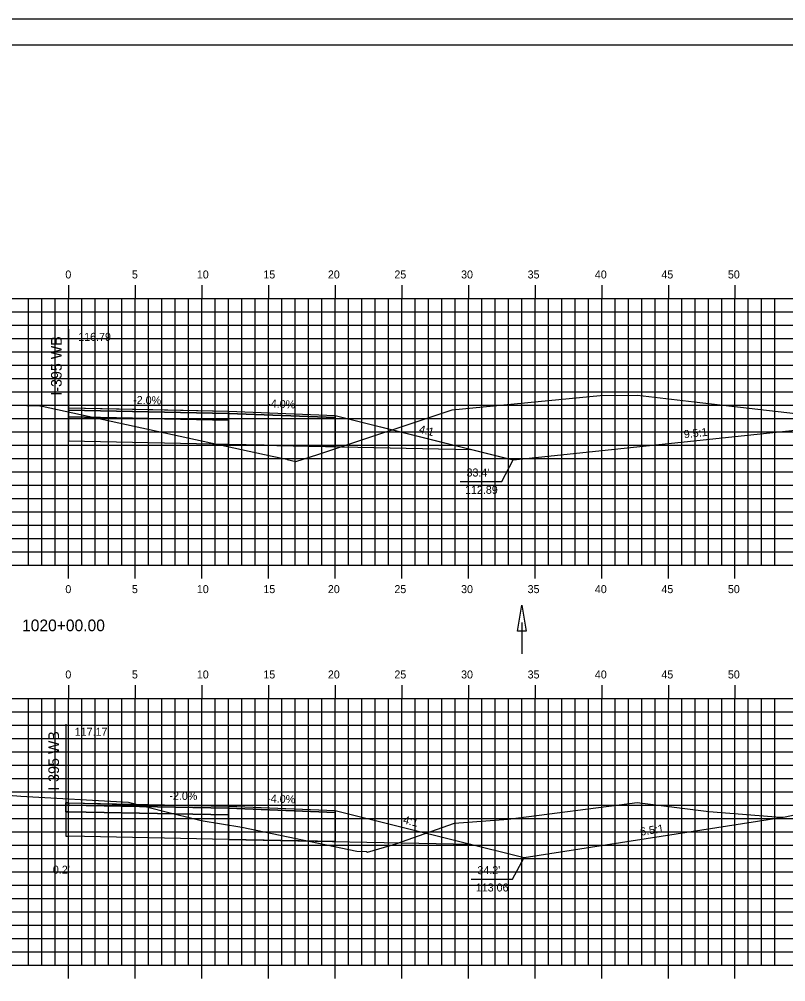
# Model space of a CAD drawing. Extents: x 853734 to 853906, y 365624 to 365734.
# Drawn here: x 853813.6 to 853871.1, y 365661.8 to 365734 of the extents above; entities that cross this region are included whole.
import ezdxf

# ---------------------------------------------------------------- set-up
doc = ezdxf.new("R2010")
doc.units = 0
for name, color, linetype in [('ANNOTATION', 7, 'Continuous'), ('BORDER', 7, 'Continuous'), ('D_Drainage_Ditch_Line', 7, 'Continuous'), ('D_Roadway_Centerline', 7, 'Continuous'), ('D_Roadway_Centerline_Text', 7, 'Continuous'), ('D_Roadway_Edge_Shoulder', 7, 'Continuous'), ('D_Roadway_Edge_TW', 7, 'Continuous'), ('D_Roadway_FinishedGrade', 7, 'Continuous'), ('D_Roadway_Pavement', 7, 'Continuous'), ('D_Roadway_SubGrade', 7, 'Continuous'), ('D_Text_Standard', 7, 'Continuous'), ('Default', 7, 'Continuous'), ('H_V ANNOTATION', 7, 'Continuous'), ('MAJOR', 7, 'Continuous'), ('MINOR', 7, 'Continuous'), ('PLOT BOUNDARY', 7, 'Continuous'), ('S_Roadway_Centerline', 7, 'Continuous')]:
    doc.layers.add(name, color=color, linetype=linetype)

msp = doc.modelspace()

# ---------------------------------------------------------------- linework, layer by layer
at = {"layer": 'ANNOTATION'}
for points in [[(853846.717, 365699.31), (853849.826, 365699.31), (853850.691, 365700.915)], [(853847.53, 365669.486), (853850.64, 365669.486), (853851.505, 365671.091)]]:
    msp.add_lwpolyline(points, dxfattribs=at)
at = {"layer": 'BORDER'}
msp.add_lwpolyline([(853742.331, 365627.027), (853902.331, 365627.027), (853902.331, 365732.027), (853742.331, 365732.027)], close=True, dxfattribs=at)
at = {"layer": 'D_Drainage_Ditch_Line'}
msp.add_line((853851.339, 365688.72), (853851.339, 365686.37), dxfattribs=at)
msp.add_lwpolyline([(853851.667, 365688.064), (853851.011, 365688.064), (853851.339, 365690.032)], close=True, dxfattribs=at)
at = {"layer": 'D_Roadway_Centerline'}
for p, q in [((853850.691, 365700.915), (853878.26, 365703.831)), ((853829.332, 365702.075), (853847.505, 365701.711)), ((853851.505, 365671.091), (853870.947, 365674.131)), ((853829.331, 365672.455), (853847.505, 365672.091))]:
    msp.add_line(p, q, dxfattribs=at)
for points in [[(853817.323, 365704.815), (853817.33, 365704.815), (853817.331, 365704.815), (853823.65, 365704.688), (853829.332, 365704.575), (853837.331, 365704.255)], [(853837.331, 365704.255), (853850.691, 365700.915)], [(853817.122, 365675.199), (853817.136, 365675.199), (853817.331, 365675.195), (853822.774, 365675.086), (853829.326, 365674.955), (853829.331, 365674.955), (853837.331, 365674.635)], [(853837.331, 365674.635), (853851.505, 365671.091)]]:
    msp.add_lwpolyline(points, dxfattribs=at)
at = {"layer": 'D_Roadway_Edge_Shoulder'}
for points in [[(853817.331, 365704.815), (853817.323, 365704.815), (853817.323, 365704.649), (853817.331, 365704.648)], [(853829.332, 365704.575), (853837.331, 365704.255), (853837.331, 365704.088), (853829.332, 365704.408)], [(853817.331, 365675.195), (853817.122, 365675.199), (853817.122, 365675.033), (853817.331, 365675.029)], [(853829.331, 365674.955), (853837.331, 365674.635), (853837.331, 365674.469), (853829.331, 365674.789)]]:
    msp.add_lwpolyline(points, close=True, dxfattribs=at)
at = {"layer": 'D_Roadway_Edge_TW'}
for points in [[(853817.331, 365704.815), (853829.332, 365704.575), (853829.332, 365704.408), (853817.331, 365704.648)], [(853817.331, 365675.195), (853829.331, 365674.955), (853829.331, 365674.789), (853817.331, 365675.029)]]:
    msp.add_lwpolyline(points, close=True, dxfattribs=at)
for points in [[(853829.332, 365704.575), (853829.332, 365704.408)], [(853829.331, 365674.955), (853829.331, 365674.789)]]:
    msp.add_lwpolyline(points, dxfattribs=at)
at = {"layer": 'D_Roadway_FinishedGrade'}
for p, q in [((853817.122, 365675.199), (853817.122, 365674.949)), ((853817.331, 365675.195), (853817.331, 365674.945)), ((853829.331, 365674.955), (853829.331, 365674.705)), ((853837.331, 365674.635), (853837.331, 365674.385))]:
    msp.add_line(p, q, dxfattribs=at)
at = {"layer": 'D_Roadway_Pavement'}
for points in [[(853817.331, 365704.648), (853817.323, 365704.649), (853817.323, 365704.149), (853817.331, 365704.148)], [(853817.331, 365704.648), (853829.332, 365704.408), (853829.332, 365703.908), (853817.331, 365704.148)], [(853817.331, 365675.029), (853817.122, 365675.033), (853817.122, 365674.533), (853817.331, 365674.529)], [(853817.331, 365675.029), (853829.331, 365674.789), (853829.331, 365674.289), (853817.331, 365674.529)]]:
    msp.add_lwpolyline(points, close=True, dxfattribs=at)
for points in [[(853829.332, 365704.408), (853829.332, 365703.908)], [(853829.332, 365704.408), (853829.332, 365703.908)], [(853829.331, 365674.789), (853829.331, 365674.289)], [(853829.331, 365674.789), (853829.331, 365674.289)]]:
    msp.add_lwpolyline(points, dxfattribs=at)
at = {"layer": 'D_Roadway_SubGrade'}
for p, q in [((853817.323, 365710.719), (853817.323, 365702.315)), ((853817.122, 365681.103), (853817.122, 365672.699))]:
    msp.add_line(p, q, dxfattribs=at)
for points in [[(853817.331, 365704.148), (853817.323, 365704.149), (853817.323, 365704.649), (853817.323, 365704.815), (853817.323, 365702.315), (853817.331, 365702.315)], [(853829.332, 365703.908), (853829.332, 365704.408), (853837.331, 365704.088), (853837.331, 365704.255), (853837.331, 365701.915), (853829.332, 365702.075)], [(853817.331, 365704.148), (853829.332, 365703.908), (853829.332, 365702.075), (853817.331, 365702.315)], [(853817.331, 365674.529), (853817.122, 365674.533), (853817.122, 365675.033), (853817.122, 365675.199), (853817.122, 365672.699), (853817.331, 365672.695)], [(853829.331, 365674.289), (853829.331, 365674.789), (853837.331, 365674.469), (853837.331, 365674.635), (853837.331, 365672.295), (853829.331, 365672.455)], [(853817.331, 365674.529), (853829.331, 365674.289), (853829.331, 365672.455), (853817.331, 365672.695)]]:
    msp.add_lwpolyline(points, close=True, dxfattribs=at)
for points in [[(853829.332, 365703.908), (853829.332, 365702.075)], [(853829.331, 365674.289), (853829.331, 365672.455)]]:
    msp.add_lwpolyline(points, dxfattribs=at)
at = {"layer": 'Default'}
msp.add_lwpolyline([(853837.331, 365704.255), (853841.331, 365703.255), (853850.154, 365701.049)], dxfattribs=at)
at = {"layer": 'MAJOR'}
for p, q in [((853817.331, 365714.029), (853817.331, 365713.027)), ((853822.331, 365714.029), (853822.331, 365713.027)), ((853827.331, 365714.029), (853827.331, 365713.027)), ((853832.331, 365714.029), (853832.331, 365713.027)), ((853837.331, 365714.029), (853837.331, 365713.027)), ((853842.331, 365714.029), (853842.331, 365713.027)), ((853847.331, 365714.029), (853847.331, 365713.027)), ((853852.331, 365714.029), (853852.331, 365713.027)), ((853857.331, 365714.029), (853857.331, 365713.027)), ((853862.331, 365714.029), (853862.331, 365713.027)), ((853867.331, 365714.029), (853867.331, 365713.027)), ((853747.331, 365713.027), (853887.331, 365713.027)), ((853747.331, 365713.027), (853887.331, 365713.027)), ((853817.331, 365693.027), (853817.331, 365713.027)), ((853822.331, 365693.027), (853822.331, 365713.027)), ((853827.331, 365693.027), (853827.331, 365713.027)), ((853832.331, 365693.027), (853832.331, 365713.027)), ((853837.331, 365693.027), (853837.331, 365713.027)), ((853842.331, 365693.027), (853842.331, 365713.027)), ((853847.331, 365693.027), (853847.331, 365713.027)), ((853852.331, 365693.027), (853852.331, 365713.027)), ((853857.331, 365693.027), (853857.331, 365713.027)), ((853862.331, 365693.027), (853862.331, 365713.027)), ((853867.331, 365693.027), (853867.331, 365713.027)), ((853747.331, 365708.027), (853887.331, 365708.027)), ((853747.331, 365703.027), (853887.331, 365703.027)), ((853747.331, 365698.027), (853887.331, 365698.027)), ((853747.331, 365693.027), (853887.331, 365693.027)), ((853747.331, 365693.027), (853887.331, 365693.027)), ((853817.331, 365692.025), (853817.331, 365693.027)), ((853822.331, 365692.025), (853822.331, 365693.027)), ((853827.331, 365692.025), (853827.331, 365693.027)), ((853832.331, 365692.025), (853832.331, 365693.027)), ((853837.331, 365692.025), (853837.331, 365693.027)), ((853842.331, 365692.025), (853842.331, 365693.027)), ((853847.331, 365692.025), (853847.331, 365693.027)), ((853852.331, 365692.025), (853852.331, 365693.027)), ((853857.331, 365692.025), (853857.331, 365693.027)), ((853862.331, 365692.025), (853862.331, 365693.027)), ((853867.331, 365692.025), (853867.331, 365693.027)), ((853817.331, 365684.029), (853817.331, 365683.027)), ((853822.331, 365684.029), (853822.331, 365683.027)), ((853827.331, 365684.029), (853827.331, 365683.027)), ((853832.331, 365684.029), (853832.331, 365683.027)), ((853837.331, 365684.029), (853837.331, 365683.027)), ((853842.331, 365684.029), (853842.331, 365683.027)), ((853847.331, 365684.029), (853847.331, 365683.027)), ((853852.331, 365684.029), (853852.331, 365683.027)), ((853857.331, 365684.029), (853857.331, 365683.027)), ((853862.331, 365684.029), (853862.331, 365683.027)), ((853867.331, 365684.029), (853867.331, 365683.027)), ((853747.331, 365683.027), (853887.331, 365683.027)), ((853747.331, 365683.027), (853887.331, 365683.027)), ((853817.331, 365663.027), (853817.331, 365683.027)), ((853822.331, 365663.027), (853822.331, 365683.027)), ((853827.331, 365663.027), (853827.331, 365683.027)), ((853832.331, 365663.027), (853832.331, 365683.027)), ((853837.331, 365663.027), (853837.331, 365683.027)), ((853842.331, 365663.027), (853842.331, 365683.027)), ((853847.331, 365663.027), (853847.331, 365683.027)), ((853852.331, 365663.027), (853852.331, 365683.027)), ((853857.331, 365663.027), (853857.331, 365683.027)), ((853862.331, 365663.027), (853862.331, 365683.027)), ((853867.331, 365663.027), (853867.331, 365683.027)), ((853747.331, 365678.027), (853887.331, 365678.027)), ((853747.331, 365673.027), (853887.331, 365673.027)), ((853747.331, 365668.027), (853887.331, 365668.027)), ((853747.331, 365663.027), (853887.331, 365663.027)), ((853747.331, 365663.027), (853887.331, 365663.027)), ((853817.331, 365662.025), (853817.331, 365663.027)), ((853822.331, 365662.025), (853822.331, 365663.027)), ((853827.331, 365662.025), (853827.331, 365663.027)), ((853832.331, 365662.025), (853832.331, 365663.027)), ((853837.331, 365662.025), (853837.331, 365663.027)), ((853842.331, 365662.025), (853842.331, 365663.027)), ((853847.331, 365662.025), (853847.331, 365663.027)), ((853852.331, 365662.025), (853852.331, 365663.027)), ((853857.331, 365662.025), (853857.331, 365663.027)), ((853862.331, 365662.025), (853862.331, 365663.027)), ((853867.331, 365662.025), (853867.331, 365663.027))]:
    msp.add_line(p, q, dxfattribs=at)
at = {"layer": 'MINOR'}
for p, q in [((853814.331, 365693.027), (853814.331, 365713.027)), ((853815.331, 365693.027), (853815.331, 365713.027)), ((853816.331, 365693.027), (853816.331, 365713.027)), ((853818.331, 365693.027), (853818.331, 365713.027)), ((853819.331, 365693.027), (853819.331, 365713.027)), ((853820.331, 365693.027), (853820.331, 365713.027)), ((853821.331, 365693.027), (853821.331, 365713.027)), ((853823.331, 365693.027), (853823.331, 365713.027)), ((853824.331, 365693.027), (853824.331, 365713.027)), ((853825.331, 365693.027), (853825.331, 365713.027)), ((853826.331, 365693.027), (853826.331, 365713.027)), ((853828.331, 365693.027), (853828.331, 365713.027)), ((853829.331, 365693.027), (853829.331, 365713.027)), ((853830.331, 365693.027), (853830.331, 365713.027)), ((853831.331, 365693.027), (853831.331, 365713.027)), ((853833.331, 365693.027), (853833.331, 365713.027)), ((853834.331, 365693.027), (853834.331, 365713.027)), ((853835.331, 365693.027), (853835.331, 365713.027)), ((853836.331, 365693.027), (853836.331, 365713.027)), ((853838.331, 365693.027), (853838.331, 365713.027)), ((853839.331, 365693.027), (853839.331, 365713.027)), ((853840.331, 365693.027), (853840.331, 365713.027)), ((853841.331, 365693.027), (853841.331, 365713.027)), ((853843.331, 365693.027), (853843.331, 365713.027)), ((853844.331, 365693.027), (853844.331, 365713.027)), ((853845.331, 365693.027), (853845.331, 365713.027)), ((853846.331, 365693.027), (853846.331, 365713.027)), ((853848.331, 365693.027), (853848.331, 365713.027)), ((853849.331, 365693.027), (853849.331, 365713.027)), ((853850.331, 365693.027), (853850.331, 365713.027)), ((853851.331, 365693.027), (853851.331, 365713.027)), ((853853.331, 365693.027), (853853.331, 365713.027)), ((853854.331, 365693.027), (853854.331, 365713.027)), ((853855.331, 365693.027), (853855.331, 365713.027)), ((853856.331, 365693.027), (853856.331, 365713.027)), ((853858.331, 365693.027), (853858.331, 365713.027)), ((853859.331, 365693.027), (853859.331, 365713.027)), ((853860.331, 365693.027), (853860.331, 365713.027)), ((853861.331, 365693.027), (853861.331, 365713.027)), ((853863.331, 365693.027), (853863.331, 365713.027)), ((853864.331, 365693.027), (853864.331, 365713.027)), ((853865.331, 365693.027), (853865.331, 365713.027)), ((853866.331, 365693.027), (853866.331, 365713.027)), ((853868.331, 365693.027), (853868.331, 365713.027)), ((853869.331, 365693.027), (853869.331, 365713.027)), ((853870.331, 365693.027), (853870.331, 365713.027)), ((853747.331, 365712.027), (853887.331, 365712.027)), ((853747.331, 365711.027), (853887.331, 365711.027)), ((853747.331, 365710.027), (853887.331, 365710.027)), ((853747.331, 365709.027), (853887.331, 365709.027)), ((853747.331, 365707.027), (853887.331, 365707.027)), ((853747.331, 365706.027), (853887.331, 365706.027)), ((853747.331, 365705.027), (853887.331, 365705.027)), ((853747.331, 365704.027), (853887.331, 365704.027)), ((853747.331, 365702.027), (853887.331, 365702.027)), ((853747.331, 365701.027), (853887.331, 365701.027)), ((853747.331, 365700.027), (853887.331, 365700.027)), ((853747.331, 365699.027), (853887.331, 365699.027)), ((853747.331, 365697.027), (853887.331, 365697.027)), ((853747.331, 365696.027), (853887.331, 365696.027)), ((853747.331, 365695.027), (853887.331, 365695.027)), ((853747.331, 365694.027), (853887.331, 365694.027)), ((853814.331, 365663.027), (853814.331, 365683.027)), ((853815.331, 365663.027), (853815.331, 365683.027)), ((853816.331, 365663.027), (853816.331, 365683.027)), ((853818.331, 365663.027), (853818.331, 365683.027)), ((853819.331, 365663.027), (853819.331, 365683.027)), ((853820.331, 365663.027), (853820.331, 365683.027)), ((853821.331, 365663.027), (853821.331, 365683.027)), ((853823.331, 365663.027), (853823.331, 365683.027)), ((853824.331, 365663.027), (853824.331, 365683.027)), ((853825.331, 365663.027), (853825.331, 365683.027)), ((853826.331, 365663.027), (853826.331, 365683.027)), ((853828.331, 365663.027), (853828.331, 365683.027)), ((853829.331, 365663.027), (853829.331, 365683.027)), ((853830.331, 365663.027), (853830.331, 365683.027)), ((853831.331, 365663.027), (853831.331, 365683.027)), ((853833.331, 365663.027), (853833.331, 365683.027)), ((853834.331, 365663.027), (853834.331, 365683.027)), ((853835.331, 365663.027), (853835.331, 365683.027)), ((853836.331, 365663.027), (853836.331, 365683.027)), ((853838.331, 365663.027), (853838.331, 365683.027)), ((853839.331, 365663.027), (853839.331, 365683.027)), ((853840.331, 365663.027), (853840.331, 365683.027)), ((853841.331, 365663.027), (853841.331, 365683.027)), ((853843.331, 365663.027), (853843.331, 365683.027)), ((853844.331, 365663.027), (853844.331, 365683.027)), ((853845.331, 365663.027), (853845.331, 365683.027)), ((853846.331, 365663.027), (853846.331, 365683.027)), ((853848.331, 365663.027), (853848.331, 365683.027)), ((853849.331, 365663.027), (853849.331, 365683.027)), ((853850.331, 365663.027), (853850.331, 365683.027)), ((853851.331, 365663.027), (853851.331, 365683.027)), ((853853.331, 365663.027), (853853.331, 365683.027)), ((853854.331, 365663.027), (853854.331, 365683.027)), ((853855.331, 365663.027), (853855.331, 365683.027)), ((853856.331, 365663.027), (853856.331, 365683.027)), ((853858.331, 365663.027), (853858.331, 365683.027)), ((853859.331, 365663.027), (853859.331, 365683.027)), ((853860.331, 365663.027), (853860.331, 365683.027)), ((853861.331, 365663.027), (853861.331, 365683.027)), ((853863.331, 365663.027), (853863.331, 365683.027)), ((853864.331, 365663.027), (853864.331, 365683.027)), ((853865.331, 365663.027), (853865.331, 365683.027)), ((853866.331, 365663.027), (853866.331, 365683.027)), ((853868.331, 365663.027), (853868.331, 365683.027)), ((853869.331, 365663.027), (853869.331, 365683.027)), ((853870.331, 365663.027), (853870.331, 365683.027)), ((853747.331, 365682.027), (853887.331, 365682.027)), ((853747.331, 365681.027), (853887.331, 365681.027)), ((853747.331, 365680.027), (853887.331, 365680.027)), ((853747.331, 365679.027), (853887.331, 365679.027)), ((853747.331, 365677.027), (853887.331, 365677.027)), ((853747.331, 365676.027), (853887.331, 365676.027)), ((853747.331, 365675.027), (853887.331, 365675.027)), ((853747.331, 365674.027), (853887.331, 365674.027)), ((853747.331, 365672.027), (853887.331, 365672.027)), ((853747.331, 365671.027), (853887.331, 365671.027)), ((853747.331, 365670.027), (853887.331, 365670.027)), ((853747.331, 365669.027), (853887.331, 365669.027)), ((853747.331, 365667.027), (853887.331, 365667.027)), ((853747.331, 365666.027), (853887.331, 365666.027)), ((853747.331, 365665.027), (853887.331, 365665.027)), ((853747.331, 365664.027), (853887.331, 365664.027))]:
    msp.add_line(p, q, dxfattribs=at)
at = {"layer": 'PLOT BOUNDARY'}
msp.add_lwpolyline([(853734.238, 365623.968), (853904.238, 365623.968), (853904.238, 365733.968), (853734.238, 365733.968)], close=True, dxfattribs=at)
at = {"layer": 'S_Roadway_Centerline'}
for points in [[(853812.276, 365705.044), (853815.177, 365704.969), (853815.27, 365704.964), (853815.339, 365704.953), (853832.608, 365701.211), (853833.575, 365700.998), (853833.71, 365700.979), (853833.733, 365700.958), (853834.393, 365700.789), (853836.025, 365701.316), (853846.123, 365704.679), (853857.205, 365705.747), (853860.019, 365705.778), (853864.274, 365705.275), (853871.878, 365704.404), (853874.679, 365704.062), (853877.708, 365703.82), (853878.26, 365703.831), (853881.928, 365704.53), (853887.331, 365705.898)], [(853811.863, 365675.837), (853813.755, 365675.697), (853821.827, 365675.24), (853824.464, 365674.566), (853827.275, 365673.871), (853830.33, 365673.374), (853838.95, 365671.586), (853839.68, 365671.539), (853839.755, 365671.509), (853841.878, 365672.13), (853846.275, 365673.685), (853850.313, 365673.969), (853859.98, 365675.212), (853865.378, 365674.554), (853870.715, 365674.134), (853870.947, 365674.131), (853871.098, 365674.158), (853881.972, 365676.502), (853882.85, 365676.699), (853887.331, 365677.689)]]:
    msp.add_lwpolyline(points, dxfattribs=at)

# ---------------------------------------------------------------- texts
at = {"layer": 'ANNOTATION'}
for s, height, rotation, p in [('I-395 WB', 0.8, 90, (853816.816, 365705.733)), ('-2.0%', 0.6, 358.85428, (853822.174, 365705.118)), ('-4.0%', 0.6, 357.70927, (853832.227, 365704.86)), ('4:1', 0.6, 345.96376, (853843.586, 365702.966)), ('9.5:1', 0.6, 6.03836, (853863.52, 365702.54)), ("33.4' ", 0.6, 360, (853847.186, 365699.673)), ('112.89', 0.6, 360, (853847.076, 365698.373)), ('I-395 WB', 0.8, 90, (853816.615, 365676.117)), ('-2.0%', 0.6, 358.8543, (853824.893, 365675.444)), ('-4.0%', 0.6, 357.70932, (853832.227, 365675.24)), ('4:1', 0.6, 345.96376, (853842.396, 365673.671)), ('6.5:1', 0.6, 8.88689, (853860.263, 365672.731)), ("34.2' ", 0.6, 360, (853848.005, 365669.849)), ('113.06', 0.6, 360, (853847.885, 365668.549))]:
    msp.add_text(s, height=height, rotation=rotation, dxfattribs=at).set_placement(p)
at = {"layer": 'D_Roadway_Centerline'}
for s, p in [('C', (853817.326, 365704.815)), ('L', (853817.331, 365704.807)), ('C', (853817.326, 365675.195)), ('L', (853817.331, 365675.187))]:
    msp.add_text(s, height=0.0146, dxfattribs=at).set_placement(p)
at = {"layer": 'D_Roadway_Centerline_Text'}
for s, p in [('116.79', (853818.056, 365709.847)), ('117.17', (853817.792, 365680.227))]:
    msp.add_text(s, height=0.6, dxfattribs=at).set_placement(p)
at = {"layer": 'D_Text_Standard'}
msp.add_text("0.2'", height=0.6, dxfattribs=at).set_placement((853816.156, 365669.884))
at = {"layer": 'H_V ANNOTATION'}
for s, height, p in [('0', 0.6, (853817.09, 365714.527)), ('5', 0.6, (853822.082, 365714.527)), ('10', 0.6, (853826.956, 365714.527)), ('15', 0.6, (853831.948, 365714.527)), ('20', 0.6, (853836.785, 365714.527)), ('25', 0.6, (853841.777, 365714.527)), ('30', 0.6, (853846.78, 365714.527)), ('35', 0.6, (853851.772, 365714.527)), ('40', 0.6, (853856.817, 365714.527)), ('45', 0.6, (853861.809, 365714.527)), ('50', 0.6, (853866.796, 365714.527)), ('0', 0.6, (853817.09, 365690.927)), ('5', 0.6, (853822.082, 365690.927)), ('10', 0.6, (853826.956, 365690.927)), ('15', 0.6, (853831.948, 365690.927)), ('20', 0.6, (853836.785, 365690.927)), ('25', 0.6, (853841.777, 365690.927)), ('30', 0.6, (853846.78, 365690.927)), ('35', 0.6, (853851.772, 365690.927)), ('40', 0.6, (853856.817, 365690.927)), ('45', 0.6, (853861.809, 365690.927)), ('50', 0.6, (853866.796, 365690.927)), ('1020+00.00', 0.875, (853813.843, 365688.07)), ('0', 0.6, (853817.09, 365684.527)), ('5', 0.6, (853822.082, 365684.527)), ('10', 0.6, (853826.956, 365684.527)), ('15', 0.6, (853831.948, 365684.527)), ('20', 0.6, (853836.785, 365684.527)), ('25', 0.6, (853841.777, 365684.527)), ('30', 0.6, (853846.78, 365684.527)), ('35', 0.6, (853851.772, 365684.527)), ('40', 0.6, (853856.817, 365684.527)), ('45', 0.6, (853861.809, 365684.527)), ('50', 0.6, (853866.796, 365684.527))]:
    msp.add_text(s, height=height, dxfattribs=at).set_placement(p)

doc.saveas('drawing.dxf')
